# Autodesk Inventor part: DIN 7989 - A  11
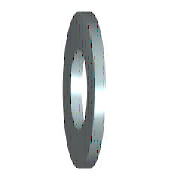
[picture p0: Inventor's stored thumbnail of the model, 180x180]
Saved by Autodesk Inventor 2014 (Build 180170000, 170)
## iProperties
Created: 2013-02
Part Number: DIN 7989 - A  11
Material: Steel, Mild
Description: Washer
Document SubType Name: Modeling
Standard: DIN 7989
Designer: Thom Tremblay
Standards Organization: DIN
Language: en-US
Size Designation: A  11
Categories: <MemberInstance><Categories><Category DisplayName="Fasteners" InternalName="e4da775c-781d-43d5-af7c-5136215cf5a6" Mnemonic="FSTN"><Category DisplayName="Washers
Density: 1 g/cm^3
Appearance: Steel
IsCustomPart: 0
Author: Thom Tremblay
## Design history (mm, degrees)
sketch "Sketch"
  geometry: C1 r 10.5 at (0, 0); C2 r 5.5 at (0, 0); 1 further point
  constraints: 2 centre point, 2 coincident
  dimensions: "d0" = 11 diameter of C2 (= SD1); "d1" = 21 diameter of C1 (= SD2)
extrude "Body" new body sketch "Sketch" distance "d2" = 8 (= SD); taper "d3" = 0 deg
workaxis "Work Axis1"
workplane "Work Plane1"
body "Solid1"
other parameters: "SD1" = 11 [user parameter; used in 1 equation term], "SD2" = 21 [user parameter; used in 1 equation term], "SD" = 8 [user parameter; used in 1 equation term], "d4" = 0, "d5" = 0, "d6" = 0, "d7" = 0
